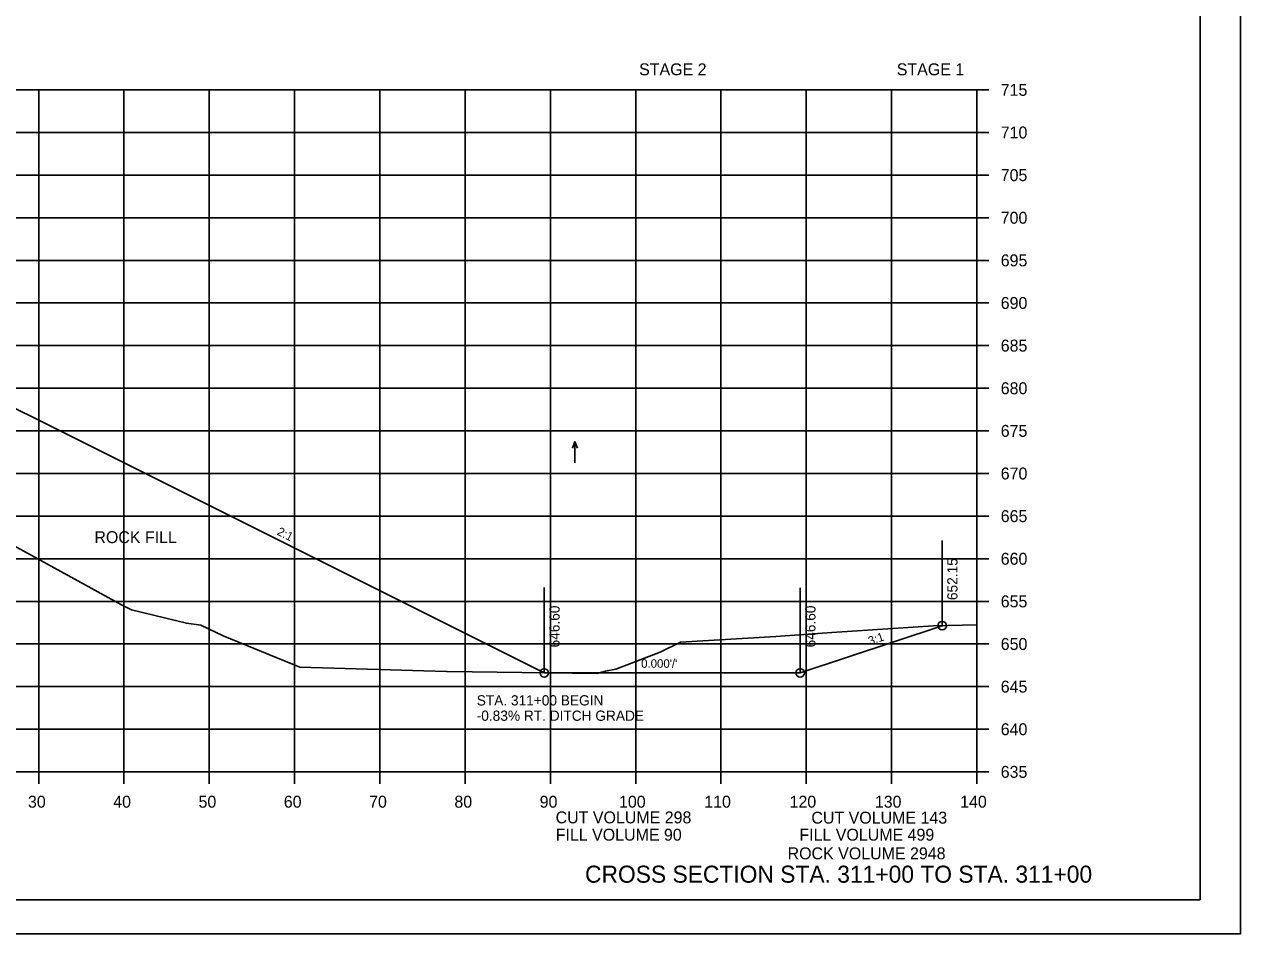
# Model space of a CAD drawing. Extents: x 1370515 to 1370849, y 383299 to 386073.
# Drawn here: x 1370706.1 to 1370848.7, y 385006.1 to 385112.8 of the extents above; entities that cross this region are included whole.
import ezdxf

# ---------------------------------------------------------------- set-up
doc = ezdxf.new("R2010")
doc.units = 0
for name, color, linetype in [('R_Axis', 7, 'Continuous'), ('R_Axis Annot', 7, 'Continuous'), ('R_Border', 7, 'Continuous'), ('R_Draft', 7, 'Continuous'), ('R_Drive', 7, 'Continuous'), ('R_Exist Surface', 7, 'Continuous'), ('R_Fin Surface', 7, 'Continuous'), ('R_Grid', 7, 'Continuous'), ('R_No Plot', 7, 'Continuous'), ('R_Water Annot', 7, 'Continuous'), ('R_Xsect Elev', 7, 'Continuous'), ('R_Xsect Slope', 7, 'Continuous')]:
    doc.layers.add(name, color=color, linetype=linetype)

msp = doc.modelspace()

# ---------------------------------------------------------------- linework, layer by layer
at = {"layer": 'R_Axis'}
for p, q in [((1370819.2, 385105.11), (1370816.4, 385105.11)), ((1370817.8, 385025.11), (1370817.8, 385105.11)), ((1370819.2, 385100.11), (1370816.4, 385100.11)), ((1370819.2, 385095.11), (1370816.4, 385095.11)), ((1370819.2, 385090.11), (1370816.4, 385090.11)), ((1370819.2, 385085.11), (1370816.4, 385085.11)), ((1370819.2, 385080.11), (1370816.4, 385080.11)), ((1370819.2, 385075.11), (1370816.4, 385075.11)), ((1370819.2, 385070.11), (1370816.4, 385070.11)), ((1370819.2, 385065.11), (1370816.4, 385065.11)), ((1370819.2, 385060.11), (1370816.4, 385060.11)), ((1370819.2, 385055.11), (1370816.4, 385055.11)), ((1370819.2, 385050.11), (1370816.4, 385050.11)), ((1370819.2, 385045.11), (1370816.4, 385045.11)), ((1370819.2, 385040.11), (1370816.4, 385040.11)), ((1370819.2, 385035.11), (1370816.4, 385035.11)), ((1370819.2, 385030.11), (1370816.4, 385030.11)), ((1370707.8, 385023.71), (1370707.8, 385026.51)), ((1370717.8, 385023.71), (1370717.8, 385026.51)), ((1370727.8, 385023.71), (1370727.8, 385026.51)), ((1370737.8, 385023.71), (1370737.8, 385026.51)), ((1370747.8, 385023.71), (1370747.8, 385026.51)), ((1370757.8, 385023.71), (1370757.8, 385026.51)), ((1370767.8, 385023.71), (1370767.8, 385026.51)), ((1370777.8, 385023.71), (1370777.8, 385026.51)), ((1370787.8, 385023.71), (1370787.8, 385026.51)), ((1370797.8, 385023.71), (1370797.8, 385026.51)), ((1370807.8, 385023.71), (1370807.8, 385026.51)), ((1370817.8, 385023.71), (1370817.8, 385026.51)), ((1370537.8, 385025.11), (1370817.8, 385025.11)), ((1370819.2, 385025.11), (1370816.4, 385025.11))]:
    msp.add_line(p, q, dxfattribs=at)
at = {"layer": 'R_Border'}
for q in [(1370843.98, 385215.57), (1370527.8, 385010.11)]:
    msp.add_line((1370843.98, 385010.11), q, dxfattribs=at)
at = {"layer": 'R_Exist Surface'}
msp.add_lwpolyline([(1370704.49, 385051.87), (1370717.49, 385044.69), (1370718.69, 385044.1), (1370725.13, 385042.54), (1370726.8, 385042.3), (1370729.42, 385041.08), (1370738.43, 385037.41), (1370755.6, 385036.89), (1370755.71, 385036.88), (1370773.23, 385036.64), (1370774.27, 385036.91), (1370775.47, 385037.14), (1370780.68, 385039.17), (1370783.06, 385040.31), (1370794.23, 385040.98), (1370800.79, 385041.47), (1370812.7, 385042.24), (1370817.8, 385042.36)], dxfattribs=at)
at = {"layer": 'R_Fin Surface'}
msp.add_lwpolyline([(1370622.48, 385067.93), (1370639.42, 385066.91), (1370646.52, 385069.28), (1370646.52, 385069.28), (1370651.8, 385071.04), (1370657.8, 385072.54), (1370665.8, 385072), (1370677.8, 385071.2), (1370689.8, 385070.39), (1370697.8, 385069.85), (1370703.8, 385068.35), (1370708.84, 385065.87), (1370715.24, 385062.65), (1370767.06, 385036.72), (1370767.11, 385036.72), (1370797.08, 385036.71), (1370813.73, 385042.26)], dxfattribs=at)
at = {"layer": 'R_Grid'}
for p, q in [((1370537.8, 385105.11), (1370817.8, 385105.11)), ((1370707.8, 385025.11), (1370707.8, 385105.11)), ((1370717.8, 385025.11), (1370717.8, 385105.11)), ((1370727.8, 385025.11), (1370727.8, 385105.11)), ((1370737.8, 385025.11), (1370737.8, 385105.11)), ((1370747.8, 385025.11), (1370747.8, 385105.11)), ((1370757.8, 385025.11), (1370757.8, 385105.11)), ((1370767.8, 385025.11), (1370767.8, 385105.11)), ((1370777.8, 385025.11), (1370777.8, 385105.11)), ((1370787.8, 385025.11), (1370787.8, 385105.11)), ((1370797.8, 385025.11), (1370797.8, 385105.11)), ((1370807.8, 385025.11), (1370807.8, 385105.11)), ((1370817.8, 385025.11), (1370817.8, 385105.11)), ((1370537.8, 385100.11), (1370817.8, 385100.11)), ((1370537.8, 385095.11), (1370817.8, 385095.11)), ((1370537.8, 385090.11), (1370817.8, 385090.11)), ((1370537.8, 385085.11), (1370817.8, 385085.11)), ((1370537.8, 385080.11), (1370817.8, 385080.11)), ((1370537.8, 385075.11), (1370817.8, 385075.11)), ((1370537.8, 385070.11), (1370817.8, 385070.11)), ((1370537.8, 385065.11), (1370817.8, 385065.11)), ((1370537.8, 385060.11), (1370817.8, 385060.11)), ((1370537.8, 385055.11), (1370817.8, 385055.11)), ((1370537.8, 385050.11), (1370817.8, 385050.11)), ((1370537.8, 385045.11), (1370817.8, 385045.11)), ((1370537.8, 385040.11), (1370817.8, 385040.11)), ((1370537.8, 385035.11), (1370817.8, 385035.11)), ((1370537.8, 385030.11), (1370817.8, 385030.11)), ((1370537.8, 385025.11), (1370817.8, 385025.11))]:
    msp.add_line(p, q, dxfattribs=at)
at = {"layer": 'R_No Plot'}
msp.add_line((1370515.4, 385006.13), (1370848.73, 385006.13), dxfattribs=at)
for points in [[(1370515.39, 385219.47), (1370848.73, 385219.47), (1370848.73, 385006.13), (1370515.39, 385006.13)], [(1370761.72, 385215.57), (1370761.72, 385205.69), (1370797.45, 385205.69), (1370797.45, 385202.77), (1370820.65, 385202.77), (1370820.65, 385179.56), (1370843.98, 385179.56), (1370843.98, 385010.11), (1370527.8, 385010.11), (1370527.8, 385215.57)]]:
    msp.add_lwpolyline(points, close=True, dxfattribs=at)
for centre in [(1370813.73, 385042.26), (1370767.08, 385036.71), (1370767.08, 385036.71), (1370797.08, 385036.71)]:
    msp.add_circle(centre, 0.5, dxfattribs=at)
at = {"layer": 'R_Water Annot'}
for p, q in [((1370770.68, 385063.86), (1370770.4, 385063.09)), ((1370770.68, 385061.35), (1370770.68, 385063.86)), ((1370770.68, 385063.86), (1370770.96, 385063.09))]:
    msp.add_line(p, q, dxfattribs=at)
at = {"layer": 'R_Xsect Elev'}
for p, q in [((1370813.73, 385042.26), (1370813.73, 385052.26)), ((1370767.06, 385036.72), (1370767.06, 385046.72)), ((1370797.08, 385036.71), (1370797.08, 385046.71))]:
    msp.add_line(p, q, dxfattribs=at)

# ---------------------------------------------------------------- texts
at = {"layer": 'R_Axis Annot'}
for s, p in [('STAGE 2', (1370778.2, 385106.82)), ('STAGE 1', (1370808.41, 385106.82)), ('715', (1370820.6, 385104.41)), ('710', (1370820.6, 385099.41)), ('705', (1370820.6, 385094.41)), ('700', (1370820.6, 385089.41)), ('695', (1370820.6, 385084.41)), ('690', (1370820.6, 385079.41)), ('685', (1370820.6, 385074.41)), ('680', (1370820.6, 385069.41)), ('675', (1370820.6, 385064.41)), ('670', (1370820.6, 385059.41)), ('665', (1370820.6, 385054.41)), ('ROCK FILL', (1370714.33, 385051.94)), ('660', (1370820.6, 385049.41)), ('655', (1370820.6, 385044.41)), ('650', (1370820.6, 385039.41)), ('645', (1370820.6, 385034.41)), ('640', (1370820.6, 385029.41)), ('635', (1370820.6, 385024.41)), ('30', (1370706.54, 385020.91)), ('40', (1370716.54, 385020.91)), ('50', (1370726.54, 385020.91)), ('60', (1370736.54, 385020.91)), ('70', (1370746.54, 385020.91)), ('80', (1370756.54, 385020.91)), ('90', (1370766.54, 385020.91)), ('100', (1370775.84, 385020.91)), ('110', (1370785.84, 385020.91)), ('120', (1370795.84, 385020.91)), ('130', (1370805.84, 385020.91)), ('140', (1370815.84, 385020.91)), ('CUT VOLUME 298', (1370768.41, 385019.07)), ('CUT VOLUME 143', (1370798.4, 385019.04)), ('FILL VOLUME 90', (1370768.42, 385017.04)), ('FILL VOLUME 499', (1370796.99, 385017.04)), ('ROCK VOLUME 2948', (1370795.61, 385014.85))]:
    msp.add_text(s, height=1.4, dxfattribs=at).set_placement(p)
at = {"layer": 'R_Draft'}
msp.add_text('CROSS SECTION STA. 311+00 TO STA. 311+00', height=2, dxfattribs=at).set_placement((1370771.86, 385012.11))
at = {"layer": 'R_Drive'}
for s, p in [('STA. 311+00 BEGIN', (1370759.16, 385032.9)), ('-0.83% RT. DITCH GRADE', (1370759.16, 385031.1))]:
    msp.add_text(s, height=1.2, dxfattribs=at).set_placement(p)
at = {"layer": 'R_No Plot'}
for p in [(1370718.65, 385044.05), (1370726.76, 385042.25), (1370783.02, 385040.26), (1370738.39, 385037.36), (1370775.43, 385037.09), (1370773.18, 385036.59)]:
    msp.add_text('+', height=0.1, dxfattribs=at).set_placement(p)
at = {"layer": 'R_Xsect Elev'}
for s, p in [('652.15', (1370815.53, 385045.26)), ('646.60', (1370768.88, 385039.71)), ('646.60', (1370798.88, 385039.71))]:
    msp.add_text(s, height=1.2, rotation=90, dxfattribs=at).set_placement(p)
at = {"layer": 'R_Xsect Slope'}
for s, rotation, p in [('2:1', 333.4349, (1370735.66, 385052.98)), ('3:1', 18.4349, (1370805.25, 385039.96)), ("0.000'/'", 359.9802, (1370778.44, 385037.32))]:
    msp.add_text(s, height=1, rotation=rotation, dxfattribs=at).set_placement(p)

doc.saveas('drawing.dxf')
